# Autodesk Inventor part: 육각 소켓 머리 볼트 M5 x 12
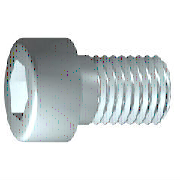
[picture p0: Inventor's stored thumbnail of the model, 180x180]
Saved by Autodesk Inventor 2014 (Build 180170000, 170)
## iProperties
Created: 2012-02
Part Number: 육각 소켓 머리 볼트 M5 x 12
Material: 강철, 연강
Description: 6각 소켓 머리 캡 나사
Document SubType Name: Modeling
Standard: ISO 4762
Designer: mdu-01
Standard Revision: Fourth edition 2004-03-01
Standards Organization: ISO
Language: ko-KR
Size Designation: M5 x 12
Categories: <MemberInstance><Categories><Category DisplayName="조임쇠" InternalName="e4da775c-781d-43d5-af7c-5136215cf5a6" Mnemonic="FSTN"><Category DisplayName="볼트" InternalN
Density: 7.75 g/cm^3
Appearance: 강철
Author: mdu-01
IsCustomPart: 1
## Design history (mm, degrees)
sketch "스케치1"
  geometry: L1 (-1.167, 0)-(12, 0); L2 (12, 0)-(12, 2.5); L3 (12, 2.5)-(2, 2.5); L4 (2, 2.5)-(1.509, 2.5); L5 (1.509, 2.5)-(0, 2.5); L6 (0, 2.5)-(0, 4.25); L7 (0, 4.25)-(-5, 4.25); L8 (-5, 4.25)-(-5, 2.309); L9 (-5, 2.309)-(-2.5, 2.309); L10 (-2.5, 2.309)-(-1.167, 0); L11 (-8.4, 0)-(15.4, 0) reference; L12 (0, -0.85)-(0, 5.1) reference; L13 (2, 2.5)-(0, 2.5)
  constraints: 22 end point, 6 parallel, 2 collinear, 2 perpendicular, 1 horizontal, 1 point on line
  dimensions: "d1" = 10 distance from line of L3.end L2 (= GEL); "d2" = 0.49086 distance of L4.end L3.end (computed from GAL); "d3" = 5 distance between parallel lines of L8 L6 (= KOH); "d4" = 2.5 distance of L8.end L9.end (= INTI); "d5" = 60 deg angle of L10 L1; "d6" = 5 diameter of L3 L1 (= GD); "d7" = 5 diameter of L5 L1 (= BDM); "d8" = 4.6188 diameter of L9 L1 (= 1.1547 x SW); "d9" = 8.5 diameter of L7 L1 (= KOD); "d26" = 12 distance between parallel lines of L12 L2 (= NLG)
revolve "본체" sketch "스케치1" stored, may be unused: angle "d10" = 90 deg
sketch "스케치2"
  geometry: L1 (0, -5.95)-(0, 5.95) reference; L2 (-5.95, 0)-(5.95, 0) reference; L3 (2.309, 0)-(1.155, -2); L4 (1.155, -2)-(-1.155, -2); L5 (-1.155, -2)-(-2.309, 0); L6 (-2.309, 0)-(-1.155, 2); L7 (-1.155, 2)-(1.155, 2); L8 (1.155, 2)-(2.309, 0); 2 further points
  constraints: 12 end point, 1 coincident, 1 horizontal alignment, 1 point on line, 12 other
extrude "슬롯" join sketch "스케치2" stored distance "d11" = 10; taper "d12" = 0 deg
workplane "Work Plane1"
fillet "Fillet2" dims "d30" = 0.1 (= R)
body "Solid1"
fillet "모깎기1" dims "d17" = 0.5 (= RR)
feature "스레드" dims "d13" = 10 (= GEL), "d14" = 0
chamfer "모따기1" distance "d15" = 0.49076 (= -0.5 x SPD + 0.5 x GD); stored, may be unused: second distance "d16" = 0.49076 (= GUL), angle "d27" = 45 deg
other parameters: "GD" = 5 [user parameter; used in 2 equation terms], "NLG" = 12 [user parameter; used in 1 equation term], "GEL" = 10 [user parameter; used in 2 equation terms], "KOD" = 8.5 [user parameter; used in 1 equation term], "KOH" = 5 [user parameter; used in 1 equation term], "INTI" = 2.5 [user parameter; used in 1 equation term], "GAL" = 0.49076 (= 0.61345 x PTC) [user parameter; used in 1 equation term], "GUL" = 0.49076 (= 0.61345 x PTC) [user parameter; used in 1 equation term], "BDM" = 5 (= NND) [user parameter; used in 1 equation term], "SW" = 4 [user parameter; used in 2 equation terms], "RR" = 0.5 [user parameter; used in 1 equation term], "SPD" = 4.01848 (= NND - 1.2269 x PTC) [user parameter; used in 1 equation term], "d19" = 0, "d28" = 0, "d29" = 0, "R" = 0.1 [user parameter; used in 1 equation term], "TOA" = 30 deg [user parameter], "GD1" = 4.01848 (= THREADDIA - 1.2269 x PTC) [user parameter], "THREADDIA" = 5 [user parameter; used in 1 equation term], "FAWI" = 45 deg [user parameter], "TPU" = 12.5 (computed from PTC) [user parameter], "PTC" = 0.8 [user parameter; used in 5 equation terms], "NND" = 5 [user parameter; used in 2 equation terms], "E0" = 4.62 (= 1.155 x SW) [user parameter]
